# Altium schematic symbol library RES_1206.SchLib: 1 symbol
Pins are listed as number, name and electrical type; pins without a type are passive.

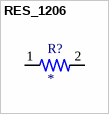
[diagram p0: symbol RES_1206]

## RES_1206
designator R?
1% 1/4W; MP: 1-2176071-4
footprint RES_1206
pins: 1, 2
